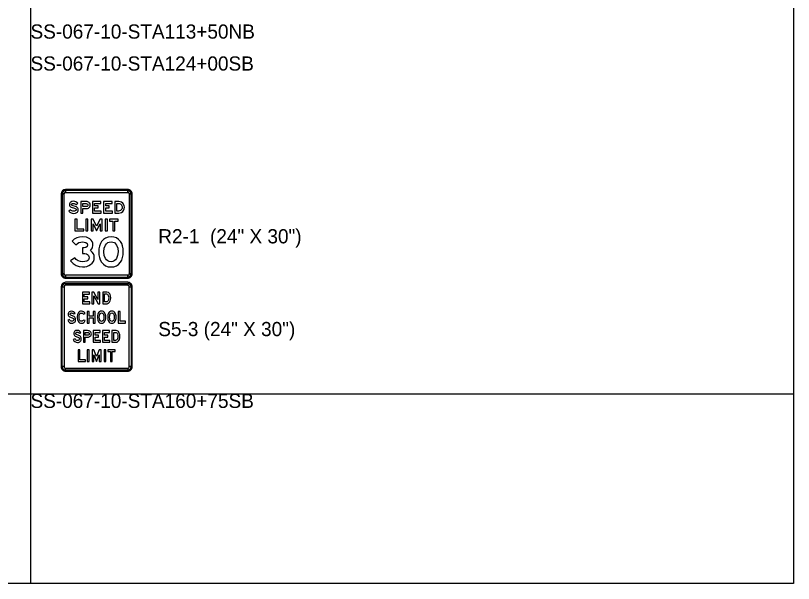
# Model space of a CAD drawing. Extents: x 1001568 to 1002149, y 1840825 to 1841423.
# Drawn here: x 1001960.23 to 1001982.13, y 1841048.13 to 1841064.12 of the extents above; entities that cross this region are included whole.
import ezdxf

# ---------------------------------------------------------------- set-up
doc = ezdxf.new("R2010")
doc.units = 0
for name, color, linetype in [('40', 7, 'Continuous'), ('R_No Plot', 7, 'Continuous'), ('SIGNS', 7, 'Continuous')]:
    doc.layers.add(name, color=color, linetype=linetype)

msp = doc.modelspace()

# ---------------------------------------------------------------- linework, layer by layer
at = {"layer": 'R_No Plot'}
for p, q in [((1001960.65, 1841110.667), (1001960.65, 1841048.127)), ((1001890.65, 1841053.469), (1001982.133, 1841053.469))]:
    msp.add_line(p, q, dxfattribs=at)
msp.add_lwpolyline([(1001886.411, 1841110.667), (1001964.232, 1841110.667), (1001964.232, 1841107.694), (1001968.454, 1841107.694), (1001968.454, 1841106.882), (1001982.133, 1841106.882), (1001982.133, 1841048.127), (1001886.411, 1841048.127)], close=True, dxfattribs=at)
at = {"layer": 'SIGNS'}
for p, q in [((1001963.387, 1841059.222), (1001961.637, 1841059.222)), ((1001961.637, 1841059.138), (1001961.637, 1841059.19)), ((1001963.387, 1841059.19), (1001963.387, 1841059.138)), ((1001961.512, 1841059.097), (1001961.512, 1841056.847)), ((1001961.543, 1841059.097), (1001961.595, 1841059.097)), ((1001963.429, 1841059.097), (1001963.481, 1841059.097)), ((1001963.512, 1841056.847), (1001963.512, 1841059.097)), ((1001961.595, 1841056.847), (1001961.543, 1841056.847)), ((1001961.637, 1841056.753), (1001961.637, 1841056.805)), ((1001963.387, 1841056.805), (1001963.387, 1841056.753)), ((1001963.481, 1841056.847), (1001963.429, 1841056.847)), ((1001961.637, 1841056.722), (1001963.387, 1841056.722)), ((1001963.387, 1841056.607), (1001961.637, 1841056.607)), ((1001961.637, 1841056.524), (1001961.637, 1841056.576)), ((1001963.387, 1841056.576), (1001963.387, 1841056.524)), ((1001961.512, 1841056.482), (1001961.512, 1841054.232)), ((1001961.543, 1841056.482), (1001961.595, 1841056.482)), ((1001963.429, 1841056.482), (1001963.481, 1841056.482)), ((1001963.512, 1841054.232), (1001963.512, 1841056.482)), ((1001961.595, 1841054.232), (1001961.543, 1841054.232)), ((1001961.637, 1841054.138), (1001961.637, 1841054.19)), ((1001963.387, 1841054.19), (1001963.387, 1841054.138)), ((1001963.481, 1841054.232), (1001963.429, 1841054.232)), ((1001961.637, 1841054.107), (1001963.387, 1841054.107))]:
    msp.add_line(p, q, dxfattribs=at)
for points in [[(1001963.387, 1841059.19), (1001961.637, 1841059.19), (1001961.637, 1841059.138), (1001963.387, 1841059.138), (1001963.387, 1841059.19), (1001963.387, 1841059.19)], [(1001961.543, 1841059.097), (1001961.543, 1841056.847), (1001961.595, 1841056.847), (1001961.595, 1841059.097), (1001961.543, 1841059.097), (1001961.543, 1841059.097)], [(1001963.481, 1841056.847), (1001963.481, 1841059.097), (1001963.429, 1841059.097), (1001963.429, 1841056.847), (1001963.481, 1841056.847), (1001963.481, 1841056.847)], [(1001961.729, 1841058.614), (1001961.757, 1841058.585), (1001961.79, 1841058.565), (1001961.826, 1841058.552), (1001961.866, 1841058.549), (1001961.912, 1841058.555), (1001961.952, 1841058.573), (1001961.971, 1841058.587), (1001961.985, 1841058.605), (1001961.993, 1841058.624), (1001961.996, 1841058.646), (1001961.993, 1841058.674), (1001961.983, 1841058.698), (1001961.968, 1841058.717), (1001961.946, 1841058.733), (1001961.913, 1841058.745), (1001961.853, 1841058.76), (1001961.831, 1841058.767), (1001961.815, 1841058.775), (1001961.806, 1841058.785), (1001961.803, 1841058.796), (1001961.806, 1841058.811), (1001961.816, 1841058.822), (1001961.834, 1841058.828), (1001961.858, 1841058.83), (1001961.88, 1841058.828), (1001961.901, 1841058.822), (1001961.919, 1841058.812), (1001961.937, 1841058.798), (1001961.981, 1841058.837), (1001961.955, 1841058.859), (1001961.926, 1841058.875), (1001961.894, 1841058.885), (1001961.86, 1841058.888), (1001961.816, 1841058.883), (1001961.781, 1841058.867), (1001961.764, 1841058.853), (1001961.753, 1841058.837), (1001961.746, 1841058.818), (1001961.743, 1841058.797), (1001961.746, 1841058.773), (1001961.756, 1841058.752), (1001961.771, 1841058.735), (1001961.793, 1841058.721), (1001961.886, 1841058.694), (1001961.908, 1841058.686), (1001961.924, 1841058.677), (1001961.933, 1841058.666), (1001961.937, 1841058.653), (1001961.935, 1841058.643), (1001961.93, 1841058.634), (1001961.922, 1841058.625), (1001961.91, 1841058.619), (1001961.889, 1841058.612), (1001961.865, 1841058.61), (1001961.839, 1841058.612), (1001961.815, 1841058.62), (1001961.794, 1841058.633), (1001961.777, 1841058.652)], [(1001962.392, 1841058.555), (1001962.639, 1841058.555), (1001962.639, 1841058.613), (1001962.452, 1841058.613), (1001962.452, 1841058.702), (1001962.551, 1841058.702), (1001962.551, 1841058.76), (1001962.452, 1841058.76), (1001962.452, 1841058.824), (1001962.634, 1841058.824), (1001962.634, 1841058.882), (1001962.392, 1841058.882)], [(1001962.709, 1841058.555), (1001962.956, 1841058.555), (1001962.956, 1841058.613), (1001962.769, 1841058.613), (1001962.769, 1841058.702), (1001962.868, 1841058.702), (1001962.868, 1841058.76), (1001962.769, 1841058.76), (1001962.769, 1841058.824), (1001962.95, 1841058.824), (1001962.95, 1841058.882), (1001962.709, 1841058.882)], [(1001961.902, 1841058.055), (1001962.149, 1841058.055), (1001962.149, 1841058.105), (1001961.961, 1841058.105), (1001961.961, 1841058.382), (1001961.902, 1841058.382)], [(1001962.209, 1841058.055), (1001962.268, 1841058.055), (1001962.268, 1841058.382), (1001962.209, 1841058.382)], [(1001962.355, 1841058.055), (1001962.413, 1841058.055), (1001962.413, 1841058.256), (1001962.509, 1841058.055), (1001962.607, 1841058.256), (1001962.607, 1841058.055), (1001962.665, 1841058.055), (1001962.665, 1841058.382), (1001962.607, 1841058.382), (1001962.509, 1841058.189), (1001962.412, 1841058.382), (1001962.355, 1841058.382)], [(1001962.755, 1841058.055), (1001962.815, 1841058.055), (1001962.815, 1841058.382), (1001962.755, 1841058.382)], [(1001962.966, 1841058.055), (1001963.024, 1841058.055), (1001963.024, 1841058.327), (1001963.119, 1841058.327), (1001963.119, 1841058.382), (1001962.872, 1841058.382), (1001962.872, 1841058.327), (1001962.966, 1841058.327)], [(1001961.779, 1841057.208), (1001961.853, 1841057.134), (1001961.934, 1841057.081), (1001962.022, 1841057.049), (1001962.118, 1841057.039), (1001962.18, 1841057.043), (1001962.238, 1841057.056), (1001962.292, 1841057.078), (1001962.342, 1841057.109), (1001962.387, 1841057.15), (1001962.42, 1841057.198), (1001962.44, 1841057.251), (1001962.446, 1841057.31), (1001962.44, 1841057.362), (1001962.42, 1841057.411), (1001962.387, 1841057.458), (1001962.342, 1841057.503), (1001962.392, 1841057.579), (1001962.408, 1841057.653), (1001962.402, 1841057.707), (1001962.385, 1841057.754), (1001962.356, 1841057.796), (1001962.316, 1841057.832), (1001962.225, 1841057.874), (1001962.116, 1841057.888), (1001962.031, 1841057.88), (1001961.954, 1841057.857), (1001961.883, 1841057.818), (1001961.819, 1841057.764), (1001961.929, 1841057.665), (1001961.97, 1841057.7), (1001962.014, 1841057.726), (1001962.062, 1841057.741), (1001962.113, 1841057.746), (1001962.162, 1841057.742), (1001962.205, 1841057.728), (1001962.244, 1841057.698), (1001962.258, 1841057.657), (1001962.244, 1841057.614), (1001962.206, 1841057.586), (1001962.163, 1841057.575), (1001962.113, 1841057.574), (1001962.113, 1841057.423), (1001962.133, 1841057.423), (1001962.183, 1841057.42), (1001962.224, 1841057.409), (1001962.256, 1841057.389), (1001962.281, 1841057.361), (1001962.294, 1841057.33), (1001962.298, 1841057.3), (1001962.294, 1841057.27), (1001962.282, 1841057.244), (1001962.263, 1841057.223), (1001962.235, 1841057.206), (1001962.182, 1841057.189), (1001962.117, 1841057.183), (1001962.053, 1841057.19), (1001961.994, 1841057.213), (1001961.939, 1841057.249), (1001961.898, 1841057.298)], [(1001961.637, 1841056.753), (1001963.387, 1841056.753), (1001963.387, 1841056.805), (1001961.637, 1841056.805), (1001961.637, 1841056.753), (1001961.637, 1841056.753)], [(1001963.387, 1841056.524), (1001961.637, 1841056.524), (1001961.637, 1841056.576), (1001963.387, 1841056.576), (1001963.387, 1841056.524), (1001963.387, 1841056.524)], [(1001961.595, 1841056.482), (1001961.595, 1841054.232), (1001961.543, 1841054.232), (1001961.543, 1841056.482), (1001961.595, 1841056.482), (1001961.595, 1841056.482)], [(1001963.429, 1841054.232), (1001963.429, 1841056.482), (1001963.481, 1841056.482), (1001963.481, 1841054.232), (1001963.429, 1841054.232), (1001963.429, 1841054.232)], [(1001962.114, 1841056.003), (1001962.318, 1841056.003), (1001962.318, 1841056.054), (1001962.164, 1841056.054), (1001962.164, 1841056.144), (1001962.261, 1841056.144), (1001962.261, 1841056.202), (1001962.164, 1841056.202), (1001962.164, 1841056.278), (1001962.307, 1841056.278), (1001962.307, 1841056.33), (1001962.114, 1841056.33)], [(1001962.377, 1841056.003), (1001962.428, 1841056.003), (1001962.428, 1841056.226), (1001962.555, 1841056.003), (1001962.601, 1841056.003), (1001962.601, 1841056.33), (1001962.544, 1841056.33), (1001962.544, 1841056.122), (1001962.428, 1841056.33), (1001962.377, 1841056.33)], [(1001961.697, 1841055.539), (1001961.716, 1841055.504), (1001961.744, 1841055.478), (1001961.779, 1841055.46), (1001961.817, 1841055.455), (1001961.839, 1841055.456), (1001961.858, 1841055.462), (1001961.876, 1841055.471), (1001961.892, 1841055.483), (1001961.904, 1841055.499), (1001961.914, 1841055.516), (1001961.919, 1841055.536), (1001961.921, 1841055.558), (1001961.918, 1841055.583), (1001961.911, 1841055.606), (1001961.898, 1841055.624), (1001961.88, 1841055.64), (1001961.803, 1841055.67), (1001961.785, 1841055.678), (1001961.772, 1841055.688), (1001961.764, 1841055.699), (1001961.761, 1841055.712), (1001961.765, 1841055.726), (1001961.777, 1841055.737), (1001961.791, 1841055.743), (1001961.807, 1841055.745), (1001961.825, 1841055.743), (1001961.84, 1841055.738), (1001961.852, 1841055.729), (1001961.861, 1841055.716), (1001961.907, 1841055.729), (1001961.892, 1841055.758), (1001961.87, 1841055.778), (1001961.843, 1841055.79), (1001961.81, 1841055.794), (1001961.77, 1841055.789), (1001961.739, 1841055.774), (1001961.726, 1841055.761), (1001961.717, 1841055.746), (1001961.711, 1841055.729), (1001961.709, 1841055.709), (1001961.712, 1841055.686), (1001961.72, 1841055.667), (1001961.732, 1841055.65), (1001961.75, 1841055.636), (1001961.827, 1841055.605), (1001961.845, 1841055.596), (1001961.857, 1841055.585), (1001961.865, 1841055.572), (1001961.868, 1841055.557), (1001961.864, 1841055.537), (1001961.853, 1841055.522), (1001961.835, 1841055.512), (1001961.814, 1841055.509), (1001961.793, 1841055.513), (1001961.773, 1841055.523), (1001961.757, 1841055.538), (1001961.747, 1841055.557)], [(1001962.138, 1841055.546), (1001962.13, 1841055.53), (1001962.118, 1841055.519), (1001962.103, 1841055.512), (1001962.085, 1841055.509), (1001962.067, 1841055.512), (1001962.052, 1841055.52), (1001962.04, 1841055.533), (1001962.03, 1841055.551), (1001962.02, 1841055.585), (1001962.017, 1841055.626), (1001962.019, 1841055.656), (1001962.024, 1841055.685), (1001962.036, 1841055.715), (1001962.052, 1841055.734), (1001962.069, 1841055.741), (1001962.09, 1841055.743), (1001962.103, 1841055.741), (1001962.116, 1841055.735), (1001962.128, 1841055.724), (1001962.139, 1841055.708), (1001962.188, 1841055.729), (1001962.171, 1841055.758), (1001962.148, 1841055.778), (1001962.119, 1841055.79), (1001962.085, 1841055.794), (1001962.055, 1841055.791), (1001962.029, 1841055.781), (1001962.007, 1841055.764), (1001961.989, 1841055.74), (1001961.978, 1841055.716), (1001961.97, 1841055.689), (1001961.965, 1841055.658), (1001961.964, 1841055.625), (1001961.965, 1841055.593), (1001961.97, 1841055.563), (1001961.978, 1841055.536), (1001961.989, 1841055.512), (1001962.007, 1841055.487), (1001962.029, 1841055.469), (1001962.054, 1841055.458), (1001962.084, 1841055.455), (1001962.119, 1841055.459), (1001962.149, 1841055.473), (1001962.172, 1841055.496), (1001962.188, 1841055.528)], [(1001962.249, 1841055.461), (1001962.301, 1841055.461), (1001962.301, 1841055.605), (1001962.416, 1841055.605), (1001962.416, 1841055.461), (1001962.473, 1841055.461), (1001962.473, 1841055.788), (1001962.416, 1841055.788), (1001962.416, 1841055.658), (1001962.301, 1841055.658), (1001962.301, 1841055.788), (1001962.249, 1841055.788)], [(1001963.121, 1841055.461), (1001963.325, 1841055.461), (1001963.325, 1841055.509), (1001963.171, 1841055.509), (1001963.171, 1841055.788), (1001963.121, 1841055.788)], [(1001961.855, 1841054.997), (1001961.874, 1841054.963), (1001961.902, 1841054.936), (1001961.937, 1841054.919), (1001961.975, 1841054.913), (1001961.997, 1841054.915), (1001962.017, 1841054.92), (1001962.034, 1841054.929), (1001962.05, 1841054.942), (1001962.063, 1841054.957), (1001962.072, 1841054.974), (1001962.077, 1841054.994), (1001962.079, 1841055.016), (1001962.077, 1841055.042), (1001962.069, 1841055.064), (1001962.056, 1841055.083), (1001962.038, 1841055.098), (1001961.961, 1841055.128), (1001961.943, 1841055.136), (1001961.93, 1841055.146), (1001961.922, 1841055.157), (1001961.92, 1841055.17), (1001961.923, 1841055.184), (1001961.935, 1841055.195), (1001961.949, 1841055.201), (1001961.965, 1841055.203), (1001961.983, 1841055.201), (1001961.998, 1841055.196), (1001962.01, 1841055.187), (1001962.019, 1841055.174), (1001962.066, 1841055.188), (1001962.05, 1841055.216), (1001962.028, 1841055.236), (1001962.001, 1841055.249), (1001961.968, 1841055.253), (1001961.928, 1841055.248), (1001961.897, 1841055.233), (1001961.884, 1841055.22), (1001961.875, 1841055.205), (1001961.869, 1841055.187), (1001961.867, 1841055.167), (1001961.87, 1841055.145), (1001961.878, 1841055.125), (1001961.89, 1841055.108), (1001961.908, 1841055.095), (1001961.985, 1841055.064), (1001962.003, 1841055.054), (1001962.016, 1841055.043), (1001962.023, 1841055.03), (1001962.026, 1841055.015), (1001962.022, 1841054.995), (1001962.011, 1841054.98), (1001961.994, 1841054.971), (1001961.972, 1841054.968), (1001961.951, 1841054.971), (1001961.932, 1841054.981), (1001961.915, 1841054.997), (1001961.905, 1841055.016)], [(1001962.415, 1841054.919), (1001962.62, 1841054.919), (1001962.62, 1841054.971), (1001962.466, 1841054.971), (1001962.466, 1841055.06), (1001962.563, 1841055.06), (1001962.563, 1841055.118), (1001962.466, 1841055.118), (1001962.466, 1841055.195), (1001962.609, 1841055.195), (1001962.609, 1841055.246), (1001962.415, 1841055.246)], [(1001962.679, 1841054.919), (1001962.883, 1841054.919), (1001962.883, 1841054.971), (1001962.73, 1841054.971), (1001962.73, 1841055.06), (1001962.827, 1841055.06), (1001962.827, 1841055.118), (1001962.73, 1841055.118), (1001962.73, 1841055.195), (1001962.873, 1841055.195), (1001962.873, 1841055.246), (1001962.679, 1841055.246)], [(1001961.992, 1841054.378), (1001962.196, 1841054.378), (1001962.196, 1841054.426), (1001962.043, 1841054.426), (1001962.043, 1841054.705), (1001961.992, 1841054.705)], [(1001962.249, 1841054.378), (1001962.301, 1841054.378), (1001962.301, 1841054.705), (1001962.249, 1841054.705)], [(1001962.382, 1841054.378), (1001962.433, 1841054.378), (1001962.433, 1841054.569), (1001962.51, 1841054.378), (1001962.587, 1841054.569), (1001962.587, 1841054.378), (1001962.639, 1841054.378), (1001962.639, 1841054.705), (1001962.587, 1841054.705), (1001962.51, 1841054.522), (1001962.433, 1841054.705), (1001962.382, 1841054.705)], [(1001962.722, 1841054.378), (1001962.775, 1841054.378), (1001962.775, 1841054.705), (1001962.722, 1841054.705)], [(1001962.901, 1841054.378), (1001962.953, 1841054.378), (1001962.953, 1841054.661), (1001963.03, 1841054.661), (1001963.03, 1841054.705), (1001962.826, 1841054.705), (1001962.826, 1841054.661), (1001962.901, 1841054.661)], [(1001961.637, 1841054.19), (1001963.387, 1841054.19), (1001963.387, 1841054.138), (1001961.637, 1841054.138), (1001961.637, 1841054.19), (1001961.637, 1841054.19)]]:
    msp.add_lwpolyline(points, close=True, dxfattribs=at)
for points in [[(1001962.065, 1841058.555), (1001962.123, 1841058.555), (1001962.123, 1841058.685), (1001962.219, 1841058.685), (1001962.251, 1841058.688), (1001962.278, 1841058.698), (1001962.301, 1841058.713), (1001962.318, 1841058.734), (1001962.329, 1841058.759), (1001962.332, 1841058.784), (1001962.33, 1841058.804), (1001962.325, 1841058.823), (1001962.315, 1841058.839), (1001962.302, 1841058.854), (1001962.285, 1841058.866), (1001962.267, 1841058.875), (1001962.248, 1841058.88), (1001962.226, 1841058.882), (1001962.065, 1841058.882), (1001962.065, 1841058.555)], [(1001962.123, 1841058.741), (1001962.123, 1841058.824), (1001962.22, 1841058.824), (1001962.24, 1841058.821), (1001962.255, 1841058.814), (1001962.267, 1841058.8), (1001962.271, 1841058.782), (1001962.267, 1841058.765), (1001962.257, 1841058.752), (1001962.241, 1841058.744), (1001962.224, 1841058.741), (1001962.123, 1841058.741)], [(1001963.025, 1841058.555), (1001963.133, 1841058.555), (1001963.173, 1841058.56), (1001963.212, 1841058.576), (1001963.247, 1841058.601), (1001963.272, 1841058.634), (1001963.287, 1841058.673), (1001963.292, 1841058.72), (1001963.287, 1841058.765), (1001963.272, 1841058.804), (1001963.248, 1841058.836), (1001963.213, 1841058.861), (1001963.175, 1841058.877), (1001963.136, 1841058.882), (1001963.025, 1841058.882), (1001963.025, 1841058.555)], [(1001963.083, 1841058.613), (1001963.083, 1841058.826), (1001963.13, 1841058.826), (1001963.152, 1841058.824), (1001963.172, 1841058.818), (1001963.189, 1841058.809), (1001963.204, 1841058.796), (1001963.216, 1841058.78), (1001963.224, 1841058.763), (1001963.229, 1841058.743), (1001963.231, 1841058.721), (1001963.228, 1841058.691), (1001963.219, 1841058.666), (1001963.203, 1841058.645), (1001963.179, 1841058.628), (1001963.154, 1841058.617), (1001963.13, 1841058.613), (1001963.083, 1841058.613)], [(1001963.263, 1841057.469), (1001963.258, 1841057.553), (1001963.242, 1841057.63), (1001963.217, 1841057.698), (1001963.181, 1841057.759), (1001963.13, 1841057.816), (1001963.069, 1841057.856), (1001962.998, 1841057.88), (1001962.917, 1841057.888), (1001962.836, 1841057.88), (1001962.765, 1841057.855), (1001962.704, 1841057.815), (1001962.653, 1841057.758), (1001962.616, 1841057.697), (1001962.591, 1841057.628), (1001962.575, 1841057.551), (1001962.57, 1841057.467), (1001962.575, 1841057.382), (1001962.59, 1841057.306), (1001962.615, 1841057.236), (1001962.65, 1841057.174), (1001962.701, 1841057.115), (1001962.762, 1841057.073), (1001962.833, 1841057.047), (1001962.912, 1841057.039), (1001962.995, 1841057.047), (1001963.068, 1841057.072), (1001963.13, 1841057.113), (1001963.182, 1841057.172), (1001963.217, 1841057.233), (1001963.242, 1841057.304), (1001963.258, 1841057.382), (1001963.263, 1841057.469)], [(1001963.114, 1841057.465), (1001963.103, 1841057.365), (1001963.071, 1841057.28), (1001963.041, 1841057.238), (1001963.006, 1841057.209), (1001962.964, 1841057.191), (1001962.917, 1841057.185), (1001962.868, 1841057.191), (1001962.825, 1841057.208), (1001962.789, 1841057.237), (1001962.759, 1841057.277), (1001962.726, 1841057.361), (1001962.715, 1841057.465), (1001962.726, 1841057.568), (1001962.759, 1841057.653), (1001962.789, 1841057.694), (1001962.826, 1841057.724), (1001962.868, 1841057.741), (1001962.917, 1841057.747), (1001962.967, 1841057.741), (1001963.01, 1841057.724), (1001963.046, 1841057.695), (1001963.075, 1841057.654), (1001963.105, 1841057.57), (1001963.114, 1841057.465)], [(1001962.799, 1841056.33), (1001962.684, 1841056.33), (1001962.684, 1841056.003), (1001962.804, 1841056.003), (1001962.826, 1841056.008), (1001962.85, 1841056.022), (1001962.875, 1841056.049), (1001962.894, 1841056.083), (1001962.905, 1841056.123), (1001962.908, 1841056.17), (1001962.904, 1841056.216), (1001962.891, 1841056.26), (1001962.879, 1841056.284), (1001962.866, 1841056.302), (1001962.85, 1841056.316), (1001962.832, 1841056.325), (1001962.799, 1841056.33)], [(1001962.788, 1841056.057), (1001962.735, 1841056.057), (1001962.735, 1841056.281), (1001962.793, 1841056.281), (1001962.808, 1841056.278), (1001962.821, 1841056.27), (1001962.831, 1841056.257), (1001962.84, 1841056.239), (1001962.848, 1841056.206), (1001962.851, 1841056.169), (1001962.848, 1841056.131), (1001962.838, 1841056.098), (1001962.829, 1841056.08), (1001962.818, 1841056.067), (1001962.804, 1841056.059), (1001962.788, 1841056.057)], [(1001962.769, 1841055.625), (1001962.767, 1841055.659), (1001962.763, 1841055.69), (1001962.756, 1841055.716), (1001962.745, 1841055.74), (1001962.728, 1841055.764), (1001962.706, 1841055.781), (1001962.68, 1841055.791), (1001962.65, 1841055.794), (1001962.621, 1841055.791), (1001962.596, 1841055.78), (1001962.575, 1841055.763), (1001962.558, 1841055.738), (1001962.548, 1841055.715), (1001962.541, 1841055.689), (1001962.536, 1841055.659), (1001962.535, 1841055.627), (1001962.536, 1841055.593), (1001962.541, 1841055.563), (1001962.548, 1841055.536), (1001962.558, 1841055.513), (1001962.575, 1841055.487), (1001962.596, 1841055.469), (1001962.622, 1841055.458), (1001962.653, 1841055.455), (1001962.682, 1841055.458), (1001962.707, 1841055.469), (1001962.728, 1841055.487), (1001962.746, 1841055.512), (1001962.756, 1841055.536), (1001962.763, 1841055.562), (1001962.767, 1841055.592), (1001962.769, 1841055.625)], [(1001962.714, 1841055.629), (1001962.711, 1841055.587), (1001962.703, 1841055.552), (1001962.693, 1841055.533), (1001962.681, 1841055.519), (1001962.666, 1841055.511), (1001962.648, 1841055.508), (1001962.632, 1841055.511), (1001962.618, 1841055.519), (1001962.606, 1841055.533), (1001962.597, 1841055.552), (1001962.589, 1841055.586), (1001962.586, 1841055.626), (1001962.589, 1841055.666), (1001962.597, 1841055.699), (1001962.606, 1841055.719), (1001962.617, 1841055.733), (1001962.631, 1841055.741), (1001962.647, 1841055.744), (1001962.665, 1841055.742), (1001962.68, 1841055.734), (1001962.693, 1841055.721), (1001962.703, 1841055.703), (1001962.711, 1841055.67), (1001962.714, 1841055.629)], [(1001963.059, 1841055.625), (1001963.058, 1841055.659), (1001963.053, 1841055.69), (1001963.046, 1841055.716), (1001963.035, 1841055.74), (1001963.018, 1841055.764), (1001962.997, 1841055.781), (1001962.971, 1841055.791), (1001962.94, 1841055.794), (1001962.911, 1841055.791), (1001962.886, 1841055.78), (1001962.865, 1841055.763), (1001962.848, 1841055.738), (1001962.838, 1841055.715), (1001962.831, 1841055.689), (1001962.826, 1841055.659), (1001962.825, 1841055.627), (1001962.826, 1841055.593), (1001962.831, 1841055.563), (1001962.838, 1841055.536), (1001962.848, 1841055.513), (1001962.865, 1841055.487), (1001962.887, 1841055.469), (1001962.912, 1841055.458), (1001962.943, 1841055.455), (1001962.972, 1841055.458), (1001962.997, 1841055.469), (1001963.019, 1841055.487), (1001963.036, 1841055.512), (1001963.046, 1841055.536), (1001963.053, 1841055.562), (1001963.058, 1841055.592), (1001963.059, 1841055.625)], [(1001963.005, 1841055.629), (1001963.002, 1841055.587), (1001962.993, 1841055.552), (1001962.983, 1841055.533), (1001962.971, 1841055.519), (1001962.956, 1841055.511), (1001962.939, 1841055.508), (1001962.922, 1841055.511), (1001962.908, 1841055.519), (1001962.896, 1841055.533), (1001962.887, 1841055.552), (1001962.879, 1841055.586), (1001962.876, 1841055.626), (1001962.879, 1841055.666), (1001962.887, 1841055.699), (1001962.896, 1841055.719), (1001962.908, 1841055.733), (1001962.921, 1841055.741), (1001962.937, 1841055.744), (1001962.955, 1841055.742), (1001962.97, 1841055.734), (1001962.983, 1841055.721), (1001962.993, 1841055.703), (1001963.002, 1841055.67), (1001963.005, 1841055.629)], [(1001962.139, 1841054.919), (1001962.19, 1841054.919), (1001962.19, 1841055.063), (1001962.257, 1841055.063), (1001962.278, 1841055.065), (1001962.297, 1841055.069), (1001962.315, 1841055.077), (1001962.33, 1841055.087), (1001962.344, 1841055.101), (1001962.355, 1841055.117), (1001962.361, 1841055.135), (1001962.363, 1841055.155), (1001962.358, 1841055.183), (1001962.345, 1841055.208), (1001962.324, 1841055.228), (1001962.299, 1841055.241), (1001962.279, 1841055.245), (1001962.251, 1841055.246), (1001962.139, 1841055.246), (1001962.139, 1841054.919)], [(1001963.057, 1841055.246), (1001962.943, 1841055.246), (1001962.943, 1841054.919), (1001963.063, 1841054.919), (1001963.085, 1841054.924), (1001963.108, 1841054.939), (1001963.134, 1841054.966), (1001963.152, 1841054.999), (1001963.163, 1841055.04), (1001963.167, 1841055.087), (1001963.162, 1841055.133), (1001963.15, 1841055.177), (1001963.138, 1841055.2), (1001963.124, 1841055.219), (1001963.108, 1841055.233), (1001963.09, 1841055.242), (1001963.057, 1841055.246)], [(1001962.19, 1841055.118), (1001962.19, 1841055.195), (1001962.26, 1841055.195), (1001962.277, 1841055.193), (1001962.292, 1841055.185), (1001962.302, 1841055.173), (1001962.305, 1841055.156), (1001962.301, 1841055.139), (1001962.291, 1841055.126), (1001962.276, 1841055.12), (1001962.257, 1841055.118), (1001962.256, 1841055.118), (1001962.19, 1841055.118)], [(1001963.047, 1841054.973), (1001962.994, 1841054.973), (1001962.994, 1841055.197), (1001963.052, 1841055.197), (1001963.066, 1841055.195), (1001963.079, 1841055.187), (1001963.09, 1841055.174), (1001963.098, 1841055.155), (1001963.107, 1841055.123), (1001963.109, 1841055.085), (1001963.106, 1841055.047), (1001963.097, 1841055.014), (1001963.088, 1841054.996), (1001963.076, 1841054.983), (1001963.063, 1841054.976), (1001963.047, 1841054.973)]]:
    msp.add_lwpolyline(points, dxfattribs=at)
for centre, radius, start, end in [((1001961.637, 1841059.097), 0.125, 90.0002, 179.9998), ((1001961.637, 1841059.097), 0.0937, 90.0002, 179.9998), ((1001963.387, 1841059.097), 0.125, 0, 90.0002), ((1001963.387, 1841059.097), 0.0937, 0, 90.0002), ((1001961.637, 1841059.097), 0.0417, 90.0002, 179.9998), ((1001963.387, 1841059.097), 0.0417, 0, 90.0002), ((1001961.637, 1841056.847), 0.125, 179.9998, 270.0001), ((1001961.637, 1841056.847), 0.0937, 179.9998, 270.0001), ((1001961.637, 1841056.847), 0.0417, 179.9998, 270.0001), ((1001963.387, 1841056.847), 0.125, 270.0001, 0.0003), ((1001963.387, 1841056.847), 0.0937, 270.0001, 0.0003), ((1001963.387, 1841056.847), 0.0417, 270.0001, 0.0003), ((1001961.637, 1841056.482), 0.125, 90.0002, 179.9998), ((1001961.637, 1841056.482), 0.0937, 90.0002, 179.9998), ((1001963.387, 1841056.482), 0.125, 0, 90.0002), ((1001963.387, 1841056.482), 0.0937, 0, 90.0002), ((1001961.637, 1841056.482), 0.0417, 90.0002, 179.9998), ((1001963.387, 1841056.482), 0.0417, 0, 90.0002), ((1001961.637, 1841054.232), 0.125, 179.9998, 270.0001), ((1001961.637, 1841054.232), 0.0937, 179.9998, 270.0001), ((1001961.637, 1841054.232), 0.0417, 179.9998, 270.0001), ((1001963.387, 1841054.232), 0.125, 270.0001, 0.0003), ((1001963.387, 1841054.232), 0.0937, 270.0001, 0.0003), ((1001963.387, 1841054.232), 0.0417, 270.0001, 0.0003)]:
    msp.add_arc(centre, radius, start, end, dxfattribs=at)

# ---------------------------------------------------------------- texts
at = {"layer": '40'}
for s, p in [('SS-067-10-STA113+50NB', (1001960.65, 1841063.469)), ('SS-067-10-STA124+00SB', (1001960.65, 1841062.569)), ('R2-1  (24" X 30")', (1001964.247, 1841057.704)), ('S5-3 (24" X 30")', (1001964.247, 1841055.091)), ('SS-067-10-STA160+75SB', (1001960.65, 1841053.069))]:
    msp.add_text(s, height=0.4, rotation=0, dxfattribs=at).set_placement(p)

doc.saveas('drawing.dxf')
